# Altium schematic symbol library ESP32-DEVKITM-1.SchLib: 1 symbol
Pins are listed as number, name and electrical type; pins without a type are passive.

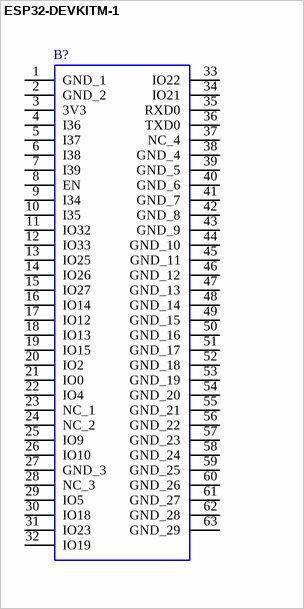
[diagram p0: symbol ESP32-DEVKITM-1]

## ESP32-DEVKITM-1
designator B?
Development Boards & Kits - Other Processors ESP32 general-purpose development board, embeds ESP32-MINI-1, with pin header; Manufacturer_Name: Espressif Systems; Geometry.Height: 2.55mm
footprint ESP32DEVKITM1
pins: 1 GND_1, 2 GND_2, 3 3V3, 4 I36, 5 I37, 6 I38, 7 I39, 8 EN, 9 I34, 10 I35, 11 IO32, 12 IO33, 13 IO25, 14 IO26, 15 IO27, 16 IO14, 17 IO12, 18 IO13, 19 IO15, 20 IO2, 21 IO0, 22 IO4, 23 NC_1, 24 NC_2, 25 IO9, 26 IO10, 27 GND_3, 28 NC_3, 29 IO5, 30 IO18, 31 IO23, 32 IO19, 33 IO22, 34 IO21, 35 RXD0, 36 TXD0, 37 NC_4, 38 GND_4, 39 GND_5, 40 GND_6, 41 GND_7, 42 GND_8, 43 GND_9, 44 GND_10, 45 GND_11, 46 GND_12, 47 GND_13, 48 GND_14, 49 GND_15, 50 GND_16, 51 GND_17, 52 GND_18, 53 GND_19, 54 GND_20, 55 GND_21, 56 GND_22, 57 GND_23, 58 GND_24, 59 GND_25, 60 GND_26, 61 GND_27, 62 GND_28, 63 GND_29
